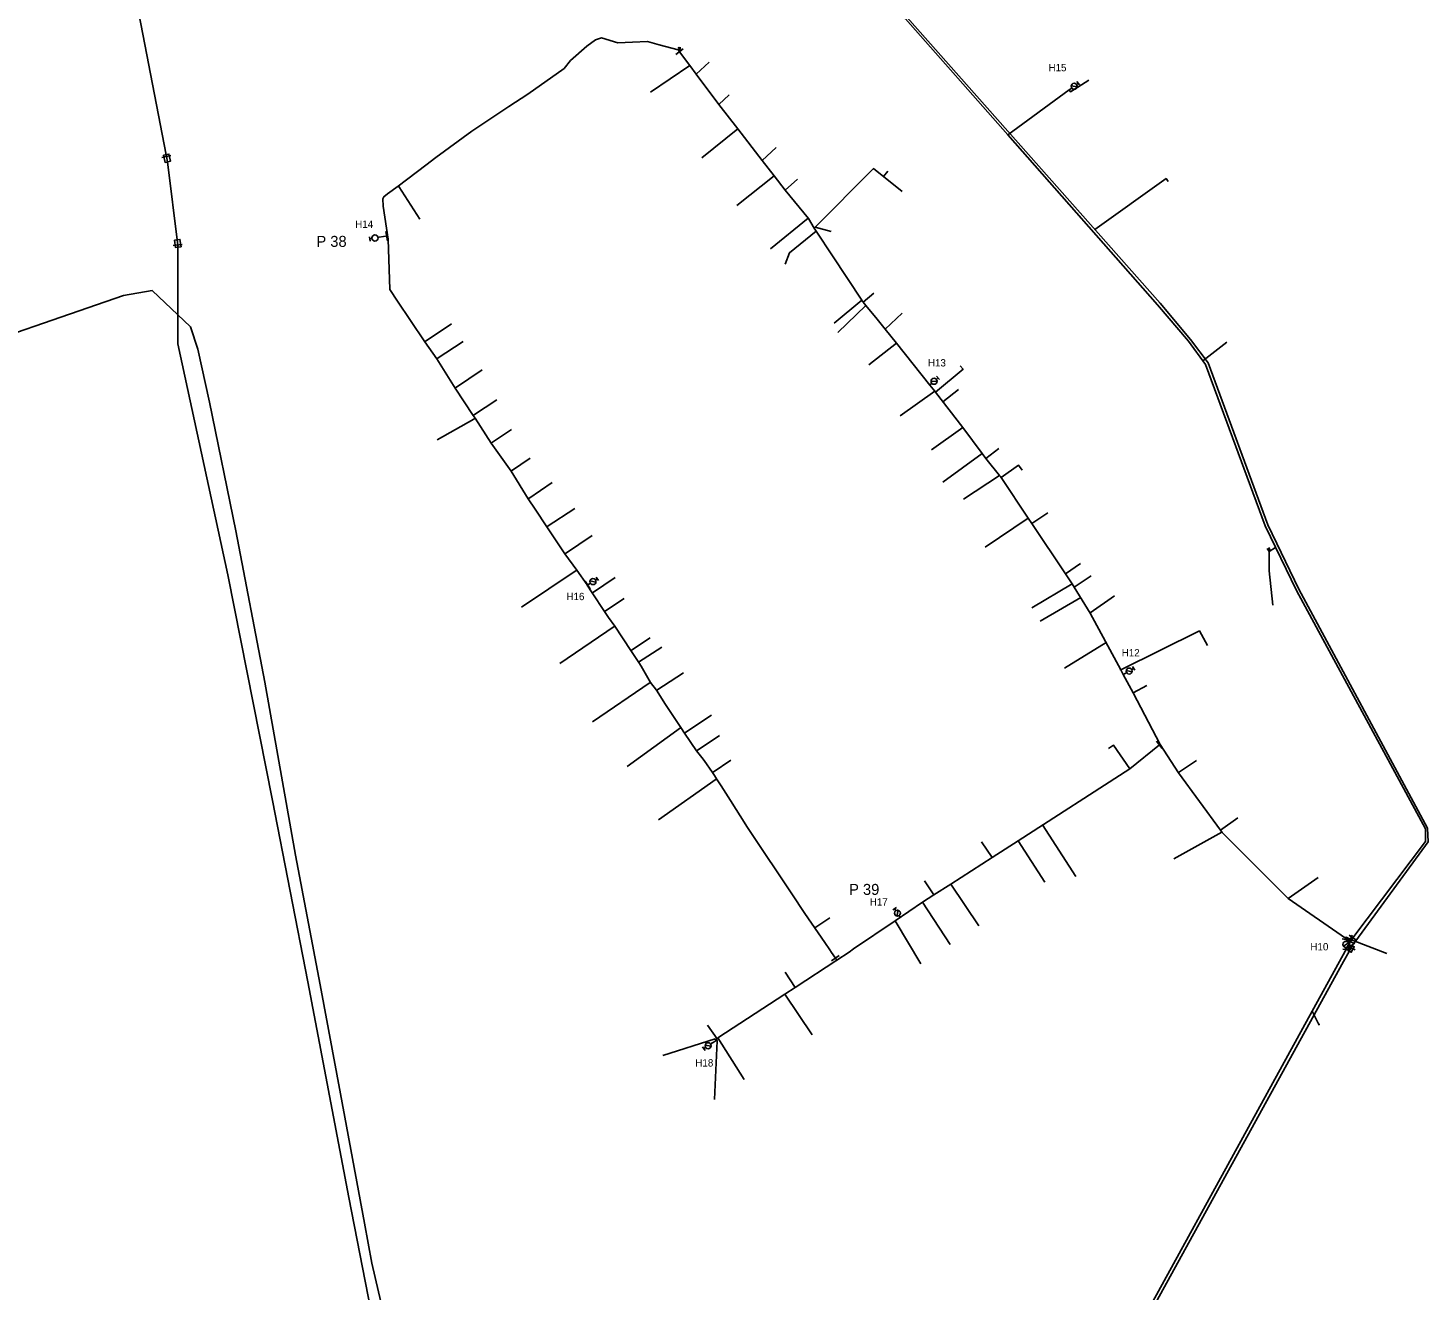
# Model space of a CAD drawing. Extents: x -548873 to -538270, y -1201997 to -1192514.
# Drawn here: x -546105.6 to -545723.4, y -1195193.3 to -1194848.6 of the extents above; entities that cross this region are included whole.
import ezdxf

# ---------------------------------------------------------------- set-up
doc = ezdxf.new("R2010")
doc.units = 0
for name, color, linetype in [('KN_HRAN_STÁTNÍ', 7, 'Continuous'), ('KN_PARC_Č', 7, 'Continuous'), ('KN_VKP_HRAN_SPORNÁ', 7, 'Continuous'), ('PK_HRAN_SPORNÁ', 7, 'Continuous'), ('PK_PARC_Čv', 7, 'Continuous'), ('Vrstva 29', 7, 'Continuous'), ('Vrstva 39', 7, 'Continuous')]:
    doc.layers.add(name, color=color, linetype=linetype)

# ---------------------------------------------------------------- blocks, each defined once
blk = doc.blocks.new('147')
at = {"layer": 'KN_HRAN_STÁTNÍ'}
blk.add_line((0, 1.27), (0, -1.27), dxfattribs=at)
blk = doc.blocks.new('160')
at = {"layer": 'KN_HRAN_STÁTNÍ'}
blk.add_circle((0, 0), 0.0458, dxfattribs=at)
blk = doc.blocks.new('133')
at = {"layer": 'KN_HRAN_STÁTNÍ'}
for p, q in [((0.28, 0), (0, 0)), ((0.54, 0.58), (1.7, -0.58)), ((1.94, 0), (2.52, 0)), ((2.52, 0.58), (2.52, -0.58))]:
    blk.add_line(p, q, dxfattribs=at)
blk.add_circle((1.11, 0), 0.825, dxfattribs=at)
blk = doc.blocks.new('132')
at = {"layer": 'KN_HRAN_STÁTNÍ'}
for p, q in [((0.3, 0), (0, 0)), ((1.96, 0), (2.52, 0)), ((2.52, 0.58), (2.52, -0.58))]:
    blk.add_line(p, q, dxfattribs=at)
blk.add_circle((1.13, 0.01), 0.825, dxfattribs=at)
blk = doc.blocks.new('150')
at = {"layer": 'KN_HRAN_STÁTNÍ'}
blk.add_line((0, 1.27), (0, -1.27), dxfattribs=at)
blk = doc.blocks.new('128')
at = {"layer": 'KN_HRAN_STÁTNÍ'}
for p, q in [((-0.19, 1.06), (-0.43, 1.15)), ((-0.36, 0.84), (-0.19, 1.06)), ((-0.19, 1.06), (-0.02, 1.25)), ((-0.19, 1.06), (0, 0)), ((0.05, 0.95), (-0.19, 1.06)), ((-0.1, 1), (0.41, 0.91)), ((-0.07, 0.82), (0.17, 0.96)), ((0.17, 0.96), (-0.02, 1.13)), ((0.17, 0.96), (0, 0)), ((0.19, 1.21), (0.17, 0.96)), ((0.17, 0.96), (0.38, 1.08)), ((0.36, 0.77), (0.17, 0.96))]:
    blk.add_line(p, q, dxfattribs=at)

msp = doc.modelspace()

# ---------------------------------------------------------------- linework, layer by layer
at = {"layer": 'KN_PARC_Č'}
for points in [[(-545923.213, -1194861.269), (-545919.609, -1194857.937)], [(-545924.883, -1194858.877), (-545935.64, -1194866.126)], [(-545838.128, -1194877.748), (-545821.326, -1194865.528), (-545820.975, -1194866.049), (-545815.984, -1194862.836)], [(-545916.958, -1194869.479), (-545914.189, -1194866.882)], [(-545911.841, -1194876.183), (-545921.648, -1194884.035)], [(-545905.181, -1194884.744), (-545901.381, -1194881.279)], [(-545890.979, -1194903.205), (-545874.763, -1194886.983), (-545866.897, -1194893.262)], [(-545872.012, -1194889.179), (-545870.87, -1194887.706)], [(-546004.51, -1194891.76), (-546004.39, -1194891.88), (-545998.579, -1194900.779)], [(-545901.871, -1194889), (-545912.058, -1194897.025)], [(-545898.858, -1194892.869), (-545895.476, -1194889.908)], [(-545814.317, -1194903.624), (-545794.891, -1194889.737), (-545794.315, -1194890.548)], [(-545892.593, -1194900.521), (-545902.875, -1194908.868)], [(-545890.713, -1194902.939), (-545886.318, -1194904.153)], [(-545890.395, -1194904.088), (-545897.656, -1194909.939), (-545898.866, -1194913.029)], [(-545877.924, -1194922.933), (-545885.503, -1194929.203)], [(-545877.581, -1194923.411), (-545874.667, -1194921.02)], [(-545876.84, -1194924.324), (-545884.51, -1194931.765)], [(-545871.557, -1194930.842), (-545866.958, -1194926.409)], [(-545997.29, -1194934.25), (-545997.18, -1194934.18), (-545989.992, -1194929.389)], [(-545994.02, -1194938.94), (-545993.9, -1194938.86), (-545986.826, -1194934.139)], [(-545784.832, -1194939.448), (-545778.33, -1194934.379)], [(-545868.509, -1194934.604), (-545876.082, -1194940.504)], [(-545988.97, -1194946.94), (-545988.86, -1194946.85), (-545981.609, -1194941.952)], [(-545857.795, -1194948.002), (-545850.303, -1194941.728), (-545851.06, -1194940.777)], [(-545858.039, -1194947.688), (-545867.514, -1194954.489)], [(-545855.809, -1194950.601), (-545851.551, -1194947.244)], [(-545984.07, -1194954.33), (-545983.93, -1194954.29), (-545977.579, -1194950.05)], [(-545983.54, -1194955.12), (-545983.86, -1194955.38), (-545993.869, -1194961.019)], [(-545979.16, -1194961.91), (-545979.05, -1194961.83), (-545973.596, -1194958.219)], [(-545850.409, -1194957.666), (-545858.921, -1194963.766)], [(-545845.127, -1194964.71), (-545855.833, -1194972.523)], [(-545844.07, -1194966.119), (-545840.531, -1194963.355)], [(-545973.73, -1194969.56), (-545973.62, -1194969.45), (-545968.458, -1194965.968)], [(-545839.909, -1194971.333), (-545835.217, -1194967.903), (-545834.17, -1194969.248)], [(-545840.353, -1194970.729), (-545850.157, -1194977.198)], [(-545969.03, -1194977.11), (-545968.9, -1194977.03), (-545962.481, -1194972.669)], [(-545963.97, -1194984.74), (-545963.86, -1194984.65), (-545956.326, -1194979.787)], [(-545832.497, -1194982.369), (-545844.258, -1194990.335)], [(-545831.499, -1194983.855), (-545827.143, -1194980.976)], [(-545959, -1194992.08), (-545958.9, -1194992), (-545951.609, -1194987.073)], [(-545766.73, -1194991.45), (-545767.273, -1194990.66)], [(-545766.516, -1194991.316), (-545766.877, -1194990.435)], [(-545765, -1194990.367), (-545766.73, -1194991.45), (-545766.757, -1194996.417), (-545766.725, -1194996.731), (-545765.77, -1195006.095)], [(-545822.362, -1194997.581), (-545818.223, -1194994.797)], [(-545955.79, -1194996.57), (-545955.91, -1194996.66), (-545970.825, -1195006.647)], [(-545951.54, -1195002.771), (-545951.48, -1195002.73), (-545945.301, -1194998.58)], [(-545819.962, -1195001.184), (-545815.353, -1194998.119)], [(-545820.571, -1195000.272), (-545831.508, -1195006.881)], [(-545948.198, -1195007.858), (-545942.857, -1195004.309)], [(-545818.206, -1195004.044), (-545829.275, -1195010.51)], [(-545815.619, -1195008.256), (-545808.976, -1195003.556)], [(-545945.43, -1195011.85), (-545945.55, -1195011.94), (-545960.435, -1195022.011)], [(-545807.257, -1195023.809), (-545785.781, -1195013.164), (-545783.556, -1195017.093)], [(-545940.98, -1195018.51), (-545940.85, -1195018.42), (-545935.723, -1195015.008)], [(-545938.888, -1195021.657), (-545932.572, -1195017.547)], [(-545811.263, -1195016.359), (-545822.599, -1195023.343)], [(-545934.02, -1195029.36), (-545933.91, -1195029.29), (-545926.615, -1195024.564)], [(-545935.61, -1195027.19), (-545935.75, -1195027.26), (-545951.498, -1195038)], [(-545803.897, -1195030.06), (-545800.167, -1195028.019)], [(-545926.39, -1195041.08), (-545926.27, -1195040.98), (-545919.022, -1195036.146)], [(-545927.39, -1195039.53), (-545927.49, -1195039.64), (-545942.01, -1195050.111)], [(-545923.05, -1195045.85), (-545922.93, -1195045.78), (-545916.781, -1195041.655)], [(-545804.797, -1195050.784), (-545809.206, -1195044.339), (-545810.57, -1195045.249)], [(-545918.69, -1195051.75), (-545918.57, -1195051.66), (-545913.717, -1195048.396)], [(-545791.473, -1195051.832), (-545786.552, -1195048.494)], [(-545917.59, -1195053.49), (-545917.71, -1195053.57), (-545933.457, -1195064.728)], [(-545780, -1195067.557), (-545775.258, -1195064.155)], [(-545828.606, -1195066.106), (-545819.537, -1195080.143)], [(-545779.634, -1195068.06), (-545792.804, -1195075.359)], [(-545842.376, -1195074.966), (-545845.299, -1195070.737)], [(-545835.293, -1195070.409), (-545828.007, -1195081.696)], [(-545858.272, -1195085.179), (-545860.831, -1195081.311)], [(-545853.677, -1195082.239), (-545846.031, -1195093.589)], [(-545761.586, -1195086.162), (-545753.37, -1195080.48)], [(-545861.426, -1195087.197), (-545853.797, -1195098.699)], [(-545890.764, -1195094.198), (-545886.655, -1195091.417)], [(-545868.848, -1195092.224), (-545861.813, -1195103.975)], [(-545745.948, -1195097.005), (-545745.764, -1195096.721), (-545743.817, -1195097.598), (-545734.587, -1195101.218)], [(-545896.193, -1195110.458), (-545898.905, -1195106.259)], [(-545898.986, -1195112.279), (-545891.493, -1195123.403)], [(-545754.97, -1195116.957), (-545753.1, -1195120.73)], [(-545917.451, -1195124.441), (-545920.099, -1195120.725)], [(-545753.23, -1195120.467), (-545752.886, -1195120.533)], [(-545917.756, -1195124.9), (-545918.035, -1195124.478), (-545932.326, -1195129.018)], [(-545917.648, -1195124.738), (-545917.446, -1195125.021), (-545918.209, -1195141.018)], [(-545917.229, -1195124.172), (-545910.039, -1195135.559)]]:
    msp.add_lwpolyline(points, dxfattribs=at)
at = {"layer": 'KN_VKP_HRAN_SPORNÁ'}
for points in [[(-546067.805, -1194883.685), (-546067.89, -1194883.26), (-546077.43, -1194833.78), (-546084.52, -1194795.48), (-546087.16, -1194783.85), (-546090.065, -1194769.166), (-546095.527, -1194742.126), (-546098.848, -1194731.817)], [(-545894.391, -1194812.852), (-545866.018, -1194846.126), (-545838.072, -1194877.812), (-545797.202, -1194924.152), (-545788.773, -1194934.13), (-545784.091, -1194940.448), (-545767.845, -1194984.478), (-545759.317, -1195002.13), (-545724.061, -1195067.122), (-545724.067, -1195070.605), (-545743.894, -1195096.929)], [(-545894.06, -1194812.626), (-545865.565, -1194845.732), (-545796.532, -1194923.714), (-545788.176, -1194933.597), (-545783.406, -1194940.035), (-545767.09, -1194984.214), (-545758.601, -1195001.771), (-545723.485, -1195066.954), (-545723.38, -1195070.726), (-545743.101, -1195097.708), (-545744.07, -1195099.034), (-545744.39, -1195099.646)], [(-545885.18, -1195102.48), (-545886.24, -1195100.89), (-545886.719, -1195100.166), (-545888.06, -1195098.14), (-545893.48, -1195090.24), (-545897.032, -1195084.939), (-545901.79, -1195077.84), (-545903.674, -1195075.016), (-545909.338, -1195066.528), (-545909.63, -1195066.09), (-545913.852, -1195059.406), (-545916.389, -1195055.391), (-545917.59, -1195053.49), (-545918.14, -1195052.62), (-545918.69, -1195051.75), (-545921.02, -1195048.48), (-545921.631, -1195047.689), (-545923.05, -1195045.85), (-545926.39, -1195041.08), (-545927.39, -1195039.53), (-545931.509, -1195033.212), (-545934.02, -1195029.36), (-545935.61, -1195027.19), (-545938.242, -1195022.735), (-545938.8, -1195021.79), (-545940.98, -1195018.51), (-545945.43, -1195011.85), (-545947.088, -1195009.459), (-545948.19, -1195007.87), (-545951.54, -1195002.771), (-545952.907, -1195000.691), (-545952.96, -1195000.61), (-545955.79, -1194996.57), (-545959, -1194992.08), (-545963.97, -1194984.74), (-545967.172, -1194979.911), (-545969.03, -1194977.11), (-545973.73, -1194969.56), (-545979.16, -1194961.91), (-545983.54, -1194955.12), (-545984.07, -1194954.33), (-545988.97, -1194946.94), (-545994.02, -1194938.94), (-545997.29, -1194934.25), (-546001.14, -1194928.45), (-546004.68, -1194923.13), (-546006.81, -1194920.01), (-546007.24, -1194906.27), (-546008.59, -1194897.21), (-546008.76, -1194895.22), (-546008.49, -1194894.66), (-546007.48, -1194893.92), (-546004.51, -1194891.76), (-545996.965, -1194886.066), (-545994.24, -1194884.01), (-545984.43, -1194876.8), (-545974.31, -1194870.06), (-545969.1, -1194866.72), (-545959.22, -1194859.66), (-545957.52, -1194857.51), (-545953.06, -1194853.58), (-545950.67, -1194851.84), (-545949, -1194851.33), (-545944.54, -1194852.67), (-545940.525, -1194852.505), (-545936.51, -1194852.34), (-545933.303, -1194853.205), (-545928.106, -1194854.607), (-545927.84, -1194854.95), (-545927.747, -1194855.088)], [(-545927.747, -1194855.088), (-545924.883, -1194858.877), (-545923.213, -1194861.269), (-545916.959, -1194869.479), (-545911.842, -1194876.182), (-545905.181, -1194884.744), (-545901.872, -1194888.999), (-545898.858, -1194892.869), (-545892.556, -1194900.567), (-545890.979, -1194903.205), (-545890.395, -1194904.087), (-545885.971, -1194910.773), (-545877.924, -1194922.933), (-545877.738, -1194923.217), (-545877.581, -1194923.411), (-545876.84, -1194924.324), (-545873.765, -1194928.119), (-545871.557, -1194930.843), (-545868.508, -1194934.604), (-545859.35, -1194946.049), (-545858.039, -1194947.688), (-545857.795, -1194948.002), (-545850.409, -1194957.666), (-545845.124, -1194964.713), (-545844.068, -1194966.121), (-545840.353, -1194970.729), (-545840.126, -1194971.011), (-545839.909, -1194971.333), (-545832.497, -1194982.369), (-545831.499, -1194983.855), (-545822.361, -1194997.583), (-545820.571, -1195000.272), (-545819.962, -1195001.184), (-545815.609, -1195008.274), (-545807.257, -1195023.809)], [(-546064.733, -1194907.845), (-546067.509, -1194885.155), (-546067.805, -1194883.685)], [(-545961.963, -1195514.079), (-545962.521, -1195511.324), (-545962.69, -1195507.6), (-545967.2, -1195478.46), (-545971.92, -1195439.14), (-545976.61, -1195401.62), (-545980.88, -1195367.42), (-545986.01, -1195331.57), (-545997.94, -1195270.1), (-546006.7, -1195225.49), (-546018, -1195167.74), (-546029.22, -1195108.89), (-546038.82, -1195059.47), (-546051.06, -1194997.81), (-546064.69, -1194934.83), (-546064.66, -1194908.44), (-546064.733, -1194907.845)], [(-545796.546, -1195044.145), (-545803.897, -1195030.059), (-545806.578, -1195025.073), (-545807.257, -1195023.809)], [(-545884.809, -1195103.036), (-545881.451, -1195100.779), (-545880.224, -1195099.946), (-545868.846, -1195092.223), (-545861.426, -1195087.197), (-545858.272, -1195085.179), (-545853.678, -1195082.239), (-545842.374, -1195074.965), (-545835.293, -1195070.409), (-545804.796, -1195050.784), (-545796.71, -1195044.26)], [(-545796.71, -1195044.26), (-545796.546, -1195044.145)], [(-545796.546, -1195044.145), (-545791.471, -1195051.836), (-545779.999, -1195067.558), (-545779.559, -1195068.162), (-545761.586, -1195086.162), (-545745.948, -1195097.005), (-545745.717, -1195097.123), (-545744.555, -1195097.421)], [(-545744.509, -1195097.934), (-545754.969, -1195116.955), (-545818.45, -1195232.396), (-545874.29, -1195333.05), (-545921.69, -1195419.837), (-545974.95, -1195516.105)], [(-545744.555, -1195097.421), (-545744.294, -1195097.519)], [(-545744.294, -1195097.519), (-545744.509, -1195097.934)], [(-545743.894, -1195096.929), (-545744.294, -1195097.519)], [(-545744.39, -1195099.646), (-545744.876, -1195100.573), (-545744.9, -1195100.62), (-545746.424, -1195103.385), (-545817.75, -1195232.784), (-545819.458, -1195235.862), (-545872.412, -1195331.277), (-545873.59, -1195333.4), (-545920.99, -1195420.223), (-545974.179, -1195516.365)], [(-545884.809, -1195103.036), (-545885.18, -1195102.48)], [(-545884.809, -1195103.036), (-545896.198, -1195110.461), (-545898.992, -1195112.283), (-545917.229, -1195124.172), (-545917.306, -1195124.222), (-545917.647, -1195124.736), (-545917.757, -1195124.9), (-545918.556, -1195125.431), (-545918.867, -1195125.637)]]:
    msp.add_lwpolyline(points, dxfattribs=at)
at = {"layer": 'PK_HRAN_SPORNÁ'}
msp.add_lwpolyline([(-546130.7, -1194939.27), (-546079.57, -1194921.64), (-546071.66, -1194920.28), (-546061.23, -1194930.15), (-546059.19, -1194936.29), (-546056.04, -1194950.69), (-546048.84, -1194985.8), (-546040.94, -1195027.13), (-546032.54, -1195074.36), (-546025.83, -1195109.75), (-546020.32, -1195139.49), (-546013.74, -1195174.77), (-546011.69, -1195185.71), (-545996.7, -1195250.16)], dxfattribs=at)
at = {"layer": 'PK_PARC_Čv'}
for points in [[(-545821.326, -1194865.528), (-545820.872, -1194865.198)], [(-546068.58, -1194883.33), (-546067.109, -1194883.035), (-546066.715, -1194884.996), (-546068.186, -1194885.291), (-546068.58, -1194883.33)], [(-546065.587, -1194906.559), (-546064.104, -1194906.332), (-546063.828, -1194908.333), (-546065.31, -1194908.54), (-546065.587, -1194906.559)], [(-546007.373, -1194905.379), (-546009.76, -1194905.702)], [(-545859.371, -1194946.023), (-545859.062, -1194945.764)], [(-545952.907, -1195000.691), (-545952.304, -1195000.308)], [(-545806.576, -1195025.077), (-545805.917, -1195024.696)], [(-545867.491, -1195091.305), (-545867.62, -1195091.1)], [(-545745.516, -1195097.175), (-545745.599, -1195097.608)], [(-545744.509, -1195098.844), (-545743.535, -1195099.355), (-545744.326, -1195100.861), (-545745.3, -1195100.35), (-545744.509, -1195098.844)], [(-545918.867, -1195125.637), (-545918.997, -1195125.723)]]:
    msp.add_lwpolyline(points, dxfattribs=at)

# ---------------------------------------------------------------- block references
for name, p, xscale, yscale, rotation in [('133', (-545820.872, -1194865.198), 0.9999999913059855, 0.9999999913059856, 37.00000193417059), ('132', (-546009.76, -1194905.702), 1.0092050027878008, 1.0092050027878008, -168.88308178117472), ('150', (-546007.669, -1194905.419), 1.0092050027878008, 1.0092050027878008, 11.116918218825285), ('133', (-545859.062, -1194945.764), 1.0000000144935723, 1.0000000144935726, 40.99999910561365), ('133', (-545952.304, -1195000.308), 0.9999999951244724, 0.9999999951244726, 33.000001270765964), ('150', (-545952.812, -1195000.631), 0.9999999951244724, 0.9999999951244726, 33.000001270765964), ('133', (-545805.917, -1195024.696), 1.0000000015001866, 1.0000000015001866, 30.99999982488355), ('133', (-545867.62, -1195091.1), 0.9999999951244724, 0.9999999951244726, 123.00000127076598), ('133', (-545745.599, -1195097.608), 0.9999999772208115, 0.9999999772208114, -100.00000028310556), ('150', (-545745.562, -1195097.414), 0.9999999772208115, 0.9999999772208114, 79.99999971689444), ('133', (-545918.997, -1195125.723), 0.9999999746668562, 0.999999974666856, -145.99999954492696)]:
    msp.add_blockref(name, p, dxfattribs=dict(at, xscale=xscale, yscale=yscale, rotation=rotation))
at = {"layer": 'Vrstva 29'}
for name, p, xscale, yscale, rotation in [('147', (-545927.747, -1194855.088), 1.000000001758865, 1.000000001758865, 125.99999933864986), ('147', (-546067.805, -1194883.685), 1.0000000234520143, 1.0000000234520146, 101.99999938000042), ('147', (-546064.733, -1194907.845), 1.000191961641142, 1.000191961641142, 97.08900113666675), ('160', (-545807.257, -1195023.809), 1.0000000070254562, 1.0000000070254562, 118.99999892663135), ('147', (-545796.71, -1195044.26), 0.9999999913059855, 0.9999999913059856, -142.99999806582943), ('160', (-545796.546, -1195044.145), 1.0000000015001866, 1.0000000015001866, -59.00000017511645), ('147', (-545744.509, -1195097.934), 0.9999999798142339, 0.9999999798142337, 61.99999866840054), ('147', (-545744.555, -1195097.421), 1.035124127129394, 1.0351241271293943, -22.503654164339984), ('147', (-545743.894, -1195096.929), 1.000000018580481, 1.000000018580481, 54.99999976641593), ('160', (-545744.294, -1195097.519), 1.0000000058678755, 1.0000000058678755, 111.99999900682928), ('147', (-545885.18, -1195102.48), 0.9999999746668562, 0.999999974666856, 124.00000045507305), ('147', (-545744.39, -1195099.646), 0.9999999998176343, 0.9999999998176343, -116.9999993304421), ('160', (-545884.809, -1195103.036), 0.9999999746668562, 0.999999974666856, -145.99999954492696), ('160', (-545918.867, -1195125.637), 0.9999999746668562, 0.999999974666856, 34.00000045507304)]:
    msp.add_blockref(name, p, dxfattribs=dict(at, xscale=xscale, yscale=yscale, rotation=rotation))
at = {"layer": 'Vrstva 39'}
msp.add_blockref('128', (-545927.747, -1194855.088), dxfattribs=at)

# ---------------------------------------------------------------- texts
at = {"layer": 'PK_PARC_Čv'}
for s, height, p in [('H15', 2, (-545826.992, -1194860.438)), ('H14', 2, (-546016.28, -1194903.162)), ('P 38', 3, (-546026.86, -1194908.352)), ('H13', 2, (-545859.912, -1194940.994)), ('H16', 2, (-545958.594, -1195004.758)), ('H12', 2, (-545806.997, -1195020.106)), ('P 39', 3, (-545881.43, -1195085.19)), ('H17', 2, (-545875.78, -1195088.1)), ('H10', 2, (-545755.479, -1195100.338)), ('H18', 2, (-545923.407, -1195132.023))]:
    msp.add_text(s, height=height, dxfattribs=at).set_placement(p)

doc.saveas('drawing.dxf')
